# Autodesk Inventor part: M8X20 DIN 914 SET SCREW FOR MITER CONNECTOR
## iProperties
Created: 2006-02
Part Number: M8X20 DIN 914 SET SCREW FOR MITER CONNECTOR
Material: Steel, Mild
Description: Hexagon Socket Set Screw
Document SubType Name: Modeling
Standard: DIN 914
Designer: Andy Moles
Standards Organization: DIN
Language: en-US
Size Designation: M8 x 12
Categories: <MemberInstance><Categories><Category DisplayName="Fasteners" InternalName="e4da775c-781d-43d5-af7c-5136215cf5a6" Mnemonic="FSTN"><Category DisplayName="Bolts"
Density: 7.86 g/cm^3
Mass: 6.57917 g
Surface Area: 6.08305 cm^2
Volume: 0.837045 cm^3
Author: Andy Moles
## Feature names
1. Body [Revolution]
2. Slot [Extrusion]
3. Chamfer1
4. Chamfer2
